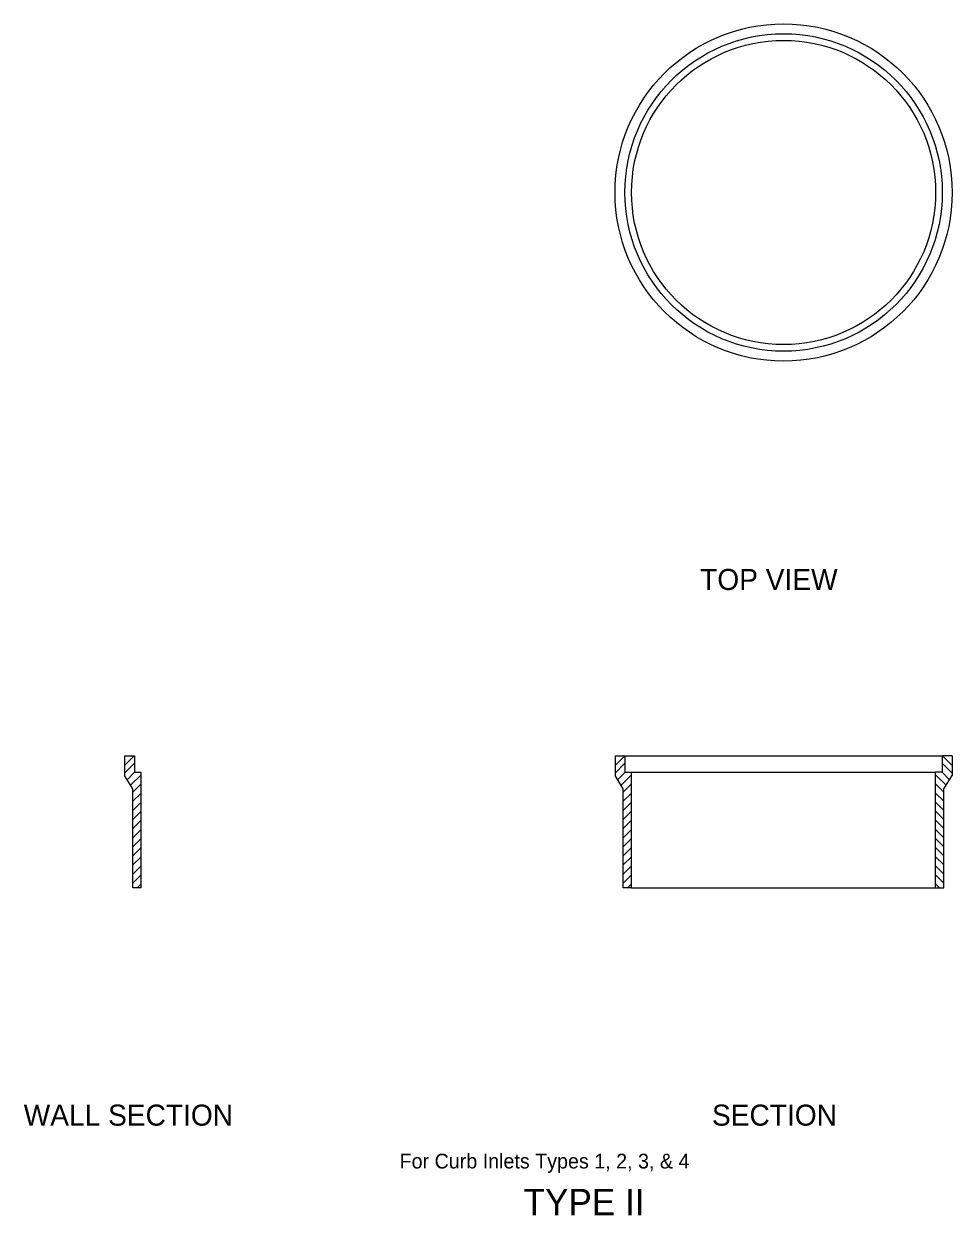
# Model space of a CAD drawing. Extents: x 4851 to 4902, y 9954.5 to 9971.9.
# Drawn here: x 4870.72 to 4876.57, y 9963.69 to 9971.19 of the extents above; entities that cross this region are included whole.
import ezdxf

# ---------------------------------------------------------------- set-up
doc = ezdxf.new("R2010")
doc.units = 0
for name, color, linetype in [('Dimension', 7, 'Continuous'), ('DSText', 7, 'Continuous'), ('SupstrConc', 7, 'Continuous'), ('TextMisc', 7, 'Continuous')]:
    doc.layers.add(name, color=color, linetype=linetype)

msp = doc.modelspace()

# ---------------------------------------------------------------- linework, layer by layer
at = {"layer": 'Dimension'}
for p, q in [((4871.3565, 9966.5828), (4871.419, 9966.5828)), ((4871.3565, 9966.5828), (4871.3565, 9966.4578)), ((4871.419, 9966.5828), (4871.419, 9966.4786)), ((4874.4484, 9966.5828), (4874.5109, 9966.5828)), ((4874.4484, 9966.5828), (4874.4484, 9966.4578)), ((4874.5109, 9966.5828), (4874.5109, 9966.4786)), ((4876.5734, 9966.5828), (4876.5109, 9966.5828)), ((4876.5109, 9966.5828), (4876.5109, 9966.4786)), ((4876.5734, 9966.5828), (4876.5734, 9966.4578)), ((4871.4086, 9966.3745), (4871.3565, 9966.4578)), ((4871.419, 9966.4786), (4871.4607, 9966.4786)), ((4871.4607, 9965.7495), (4871.4607, 9966.4786)), ((4874.5005, 9966.3745), (4874.4484, 9966.4578)), ((4874.5109, 9966.4786), (4874.5526, 9966.4786)), ((4874.5526, 9965.7495), (4874.5526, 9966.4786)), ((4876.5109, 9966.4786), (4876.4692, 9966.4786)), ((4876.4692, 9965.7495), (4876.4692, 9966.4786)), ((4876.5213, 9966.3745), (4876.5734, 9966.4578)), ((4871.4086, 9965.7495), (4871.4086, 9966.3745)), ((4874.5005, 9965.7495), (4874.5005, 9966.3745)), ((4876.5213, 9965.7495), (4876.5213, 9966.3745)), ((4871.4607, 9965.7495), (4871.4086, 9965.7495)), ((4874.5526, 9965.7495), (4874.5005, 9965.7495)), ((4876.4692, 9965.7495), (4876.5213, 9965.7495))]:
    msp.add_line(p, q, dxfattribs=at)
for radius in [1.0625, 1, 0.9583]:
    msp.add_circle((4875.5109, 9970.1309), radius, dxfattribs=at)
at = {"layer": 'SupstrConc'}
for p, q in [((4874.5109, 9966.5828), (4876.5109, 9966.5828)), ((4874.5526, 9966.4786), (4876.4692, 9966.4786)), ((4874.5526, 9965.7495), (4876.4692, 9965.7495))]:
    msp.add_line(p, q, dxfattribs=at)
at = {"layer": 'TextMisc'}
for points in [[(4871.3565, 9966.521), (4871.4177, 9966.5823)], [(4871.3565, 9966.4722), (4871.419, 9966.5347)], [(4874.4484, 9966.521), (4874.5097, 9966.5823)], [(4874.4484, 9966.4722), (4874.5109, 9966.5347)], [(4876.5734, 9966.4722), (4876.5109, 9966.5347)], [(4876.5734, 9966.521), (4876.5122, 9966.5823)], [(4871.3728, 9966.4313), (4871.4195, 9966.478)], [(4871.395, 9966.3961), (4871.4607, 9966.4618)], [(4874.4648, 9966.4313), (4874.5115, 9966.478)], [(4874.4869, 9966.3961), (4874.5526, 9966.4618)], [(4876.535, 9966.3961), (4876.4692, 9966.4618)], [(4876.5571, 9966.4313), (4876.5104, 9966.478)], [(4871.4086, 9966.3525), (4871.4611, 9966.405)], [(4874.5005, 9966.3525), (4874.553, 9966.405)], [(4876.5213, 9966.3525), (4876.4689, 9966.405)], [(4871.4086, 9966.2952), (4871.4607, 9966.3473)], [(4871.4086, 9966.238), (4871.4607, 9966.2901)], [(4874.5005, 9966.2952), (4874.5526, 9966.3473)], [(4874.5005, 9966.238), (4874.5526, 9966.2901)], [(4876.5213, 9966.2952), (4876.4692, 9966.3473)], [(4876.5213, 9966.238), (4876.4692, 9966.2901)], [(4871.4086, 9966.1807), (4871.4607, 9966.2328)], [(4874.5005, 9966.1807), (4874.5526, 9966.2328)], [(4876.5213, 9966.1807), (4876.4692, 9966.2328)], [(4871.4086, 9966.1235), (4871.4607, 9966.1756)], [(4874.5005, 9966.1235), (4874.5526, 9966.1756)], [(4876.5213, 9966.1235), (4876.4692, 9966.1756)], [(4871.4086, 9966.0662), (4871.4607, 9966.1183)], [(4874.5005, 9966.0662), (4874.5526, 9966.1183)], [(4876.5213, 9966.0662), (4876.4692, 9966.1183)], [(4871.4086, 9966.0089), (4871.4607, 9966.061)], [(4871.4086, 9965.9517), (4871.4607, 9966.0038)], [(4874.5005, 9966.0089), (4874.5526, 9966.061)], [(4874.5005, 9965.9517), (4874.5526, 9966.0038)], [(4876.5213, 9966.0089), (4876.4692, 9966.061)], [(4876.5213, 9965.9517), (4876.4692, 9966.0038)], [(4871.4086, 9965.8944), (4871.4607, 9965.9465)], [(4874.5005, 9965.8944), (4874.5526, 9965.9465)], [(4876.5213, 9965.8944), (4876.4692, 9965.9465)], [(4871.4086, 9965.8371), (4871.4607, 9965.8892)], [(4874.5005, 9965.8371), (4874.5526, 9965.8892)], [(4876.5213, 9965.8371), (4876.4692, 9965.8892)], [(4871.4086, 9965.7799), (4871.4607, 9965.832)], [(4871.4354, 9965.7494), (4871.4607, 9965.7747)], [(4874.5005, 9965.7799), (4874.5526, 9965.832)], [(4874.5274, 9965.7494), (4874.5526, 9965.7747)], [(4876.5213, 9965.7799), (4876.4692, 9965.832)], [(4876.4945, 9965.7494), (4876.4692, 9965.7747)]]:
    msp.add_lwpolyline(points, dxfattribs=at)

# ---------------------------------------------------------------- texts
at = {"layer": 'DSText'}
for s, height, p in [('TOP VIEW', 0.13253, (4874.9849, 9967.6268)), ('WALL SECTION', 0.132526, (4870.7211, 9964.2519)), ('SECTION', 0.13253, (4875.0594, 9964.2519)), ('For Curb Inlets Types 1, 2, 3, & 4', 0.092768, (4873.0903, 9963.9822)), ('TYPE II', 0.16566, (4873.8714, 9963.6879))]:
    msp.add_text(s, height=height, dxfattribs=at).set_placement(p)

doc.saveas('drawing.dxf')
